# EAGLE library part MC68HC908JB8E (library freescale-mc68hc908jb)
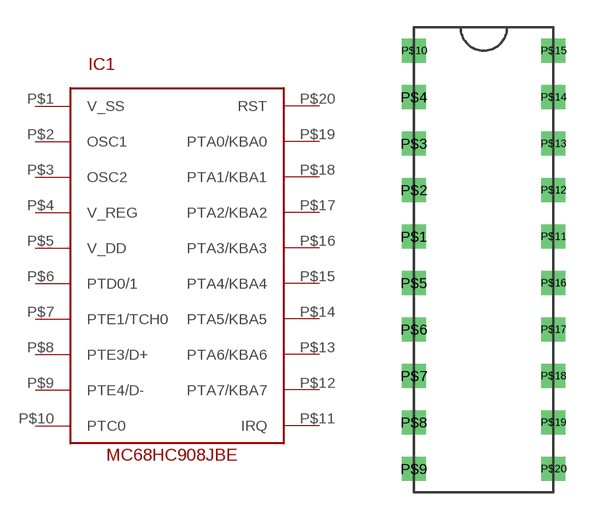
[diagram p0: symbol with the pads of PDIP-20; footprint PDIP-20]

Designator prefix -

## MC68HC908JB8EPDIP-20  [PDIP-20]
P$1  V_SS  pwr
P$2  OSC1
P$3  OSC2
P$4  V_REG
P$5  V_DD  pwr
P$6  PTD0/1
P$7  PTE1/TCH0
P$8  PTE3/D+
P$9  PTE4/D-
P$10  PTC0
P$11  IRQ
P$12  PTA7/KBA7
P$13  PTA6/KBA6
P$14  PTA5/KBA5
P$15  PTA4/KBA4
P$16  PTA3/KBA3
P$17  PTA2/KBA2
P$18  PTA1/KBA1
P$19  PTA0/KBA0
P$20  RST

## Footprint PDIP-20 (pad centres in mm)
drill 0.8 square: P$1 -3.81,1.27; P$2 -3.81,3.81; P$3 -3.81,6.35; P$4 -3.81,8.89; P$5 -3.81,-1.27; P$6 -3.81,-3.81; P$7 -3.81,-6.35; P$8 -3.81,-8.89; P$9 -3.81,-11.43; P$10 -3.81,11.43; P$11 3.81,1.27; P$12 3.81,3.81; P$13 3.81,6.35; P$14 3.81,8.89; P$15 3.81,11.43; P$16 3.81,-1.27; P$17 3.81,-3.81; P$18 3.81,-6.35; P$19 3.81,-8.89; P$20 3.81,-11.43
